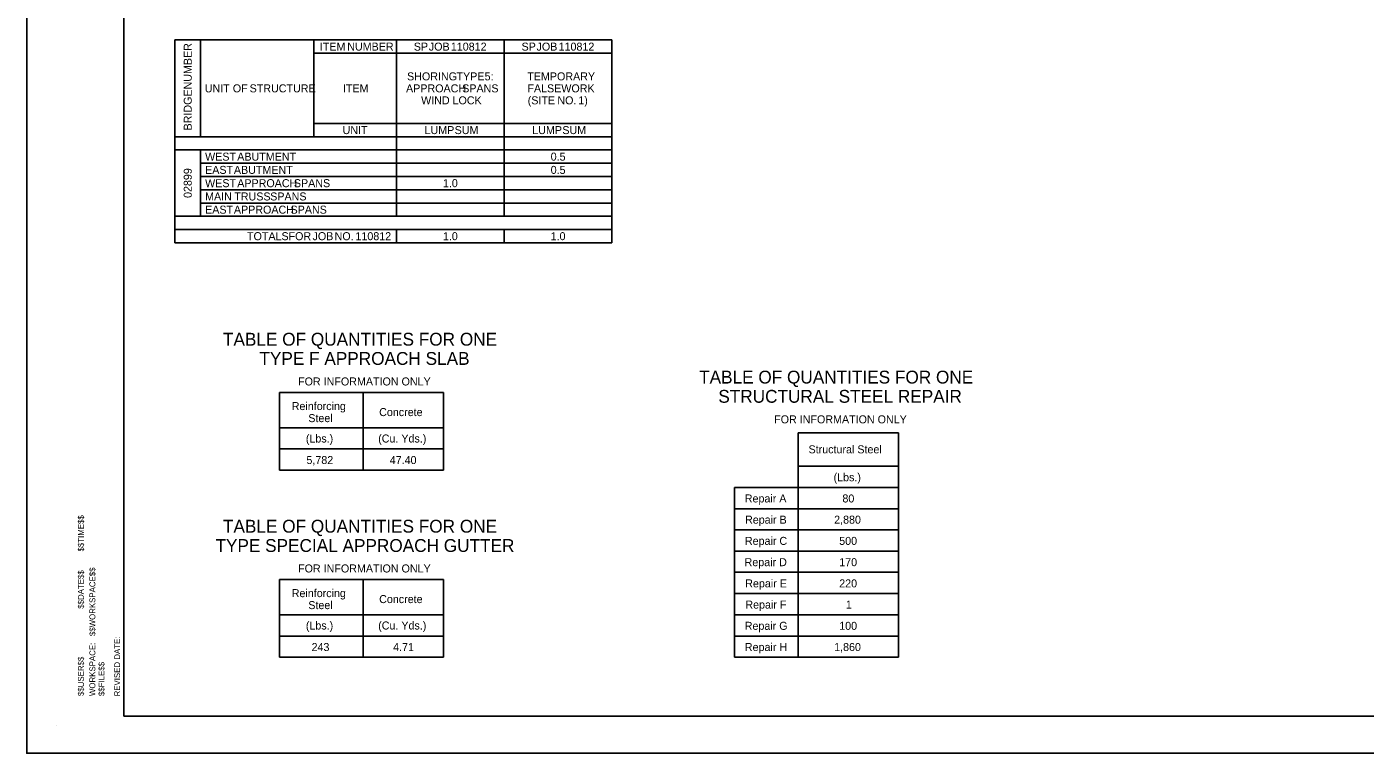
# Model space of a CAD drawing. Extents: x 188 to 14744886, y 129 to 1829278.
# Drawn here: x 187.88 to 208.75, y 128.51 to 139.85 of the extents above; entities that cross this region are included whole.
import ezdxf

# ---------------------------------------------------------------- set-up
doc = ezdxf.new("R2010")
doc.units = 0
for name, color, linetype in [('B_Text', 7, 'Continuous'), ('B_Title Text', 7, 'Continuous'), ('R_Border', 7, 'Continuous'), ('R_No Plot', 7, 'Continuous')]:
    doc.layers.add(name, color=color, linetype=linetype)

msp = doc.modelspace()

# ---------------------------------------------------------------- linework, layer by layer
at = {"layer": 'B_Text'}
for p, q in [((190.192, 139.64), (197.006, 139.64)), ((190.192, 139.64), (197.006, 139.64)), ((190.192, 136.476), (190.192, 139.64)), ((190.593, 138.131), (190.593, 139.64)), ((192.357, 138.131), (192.357, 139.64)), ((192.357, 138.131), (192.357, 139.64)), ((193.647, 136.89), (193.647, 139.64)), ((195.326, 136.89), (195.326, 139.64)), ((197.006, 136.476), (197.006, 139.64)), ((197.006, 136.476), (197.006, 139.64)), ((192.357, 139.433), (197.006, 139.433)), ((192.357, 138.338), (197.006, 138.338)), ((190.192, 138.131), (197.006, 138.131)), ((190.192, 137.924), (197.006, 137.924)), ((190.593, 136.89), (190.593, 137.924)), ((190.593, 137.717), (197.006, 137.717)), ((190.593, 137.51), (197.006, 137.51)), ((190.593, 137.303), (197.006, 137.303)), ((190.593, 137.096), (197.006, 137.096)), ((190.192, 136.89), (197.006, 136.89)), ((190.192, 136.683), (197.006, 136.683)), ((193.647, 136.476), (193.647, 136.683)), ((195.326, 136.476), (195.326, 136.683)), ((190.192, 136.476), (197.006, 136.476)), ((193.128, 132.928), (193.128, 134.139)), ((191.823, 133.26), (194.381, 133.26)), ((199.909, 132.991), (201.475, 132.991)), ((198.916, 132.329), (201.475, 132.329)), ((198.916, 131.998), (201.475, 131.998)), ((198.916, 131.667), (201.475, 131.667)), ((198.916, 131.336), (201.475, 131.336)), ((193.128, 130.011), (193.128, 131.222)), ((198.916, 131.005), (201.475, 131.005)), ((198.916, 130.673), (201.475, 130.673)), ((191.823, 130.342), (194.381, 130.342)), ((198.916, 130.342), (201.475, 130.342))]:
    msp.add_line(p, q, dxfattribs=at)
at = {"layer": 'B_Title Text'}
for p, q in [((191.823, 134.139), (194.381, 134.139)), ((191.823, 132.928), (191.823, 134.139)), ((194.381, 132.928), (194.381, 134.139)), ((191.823, 133.591), (194.381, 133.591)), ((199.909, 130.011), (199.909, 133.513)), ((199.909, 133.513), (201.475, 133.513)), ((201.475, 130.011), (201.475, 133.513)), ((191.823, 132.928), (194.381, 132.928)), ((198.916, 132.66), (201.475, 132.66)), ((198.916, 130.011), (198.916, 132.66)), ((191.823, 131.222), (194.381, 131.222)), ((191.823, 130.011), (191.823, 131.222)), ((194.381, 130.011), (194.381, 131.222)), ((191.823, 130.673), (194.381, 130.673)), ((191.823, 130.011), (194.381, 130.011)), ((198.916, 130.011), (201.475, 130.011))]:
    msp.add_line(p, q, dxfattribs=at)
at = {"layer": 'R_Border'}
for p, q in [((189.399, 129.091), (189.399, 149.937)), ((221.306, 129.091), (189.399, 129.091)), ((188.351, 128.942), (188.351, 128.942))]:
    msp.add_line(p, q, dxfattribs=at)
at = {"layer": 'R_No Plot'}
msp.add_lwpolyline([(187.883, 150.514), (221.883, 150.514), (221.883, 128.514), (187.883, 128.514)], close=True, dxfattribs=at)

# ---------------------------------------------------------------- texts
at = {"layer": 'B_Text'}
for s, height, p in [('ITEM', 0.1248, (192.452, 139.474)), (' NUMBER', 0.1248, (192.833, 139.474)), ('SP', 0.1248, (193.917, 139.474)), (' JOB', 0.1248, (194.105, 139.474)), (' 110812', 0.1248, (194.448, 139.474)), ('SP', 0.1248, (195.597, 139.474)), (' JOB', 0.1248, (195.784, 139.474)), (' 110812', 0.1248, (196.128, 139.474)), ('SHORING', 0.1248, (193.812, 139.01)), (' TYPE', 0.1248, (194.536, 139.01)), (' 5:', 0.1248, (194.974, 139.01)), ('TEMPORARY', 0.1248, (195.686, 139.01)), ('UNIT', 0.1248, (190.658, 138.823)), (' OF', 0.1248, (191.049, 138.823)), (' STRUCTURE', 0.1248, (191.311, 138.823)), ('ITEM', 0.1248, (192.812, 138.823)), ('APPROACH', 0.1248, (193.796, 138.823)), ('WIND', 0.1248, (194.031, 138.636)), (' LOCK', 0.1248, (194.475, 138.636)), (' SPANS', 0.1248, (194.625, 138.823)), ('FALSEWORK', 0.1248, (195.688, 138.823)), ('(SITE', 0.1248, (195.693, 138.636)), (' NO.', 0.1248, (196.109, 138.636)), (' 1)', 0.1248, (196.435, 138.636)), ('UNIT', 0.1248, (192.807, 138.172)), ('LUMP', 0.1248, (194.085, 138.172)), (' SUM', 0.1248, (194.507, 138.172)), ('LUMP', 0.1248, (195.764, 138.172)), (' SUM', 0.1248, (196.186, 138.172)), (' WEST', 0.1248, (190.617, 137.758)), (' ABUTMENT', 0.1248, (191.118, 137.758)), ('0.5', 0.1248, (196.051, 137.758)), (' EAST', 0.1248, (190.617, 137.551)), (' ABUTMENT', 0.1248, (191.066, 137.551)), ('0.5', 0.1248, (196.051, 137.551)), (' WEST', 0.1248, (190.617, 137.344)), (' APPROACH', 0.1248, (191.118, 137.344)), (' SPANS', 0.1248, (192.001, 137.344)), ('1.0', 0.1248, (194.371, 137.344)), (' MAIN', 0.1248, (190.617, 137.137)), (' TRUSS', 0.1248, (191.072, 137.137)), (' SPANS', 0.1248, (191.632, 137.137)), (' EAST', 0.1248, (190.617, 136.931)), (' APPROACH', 0.1248, (191.066, 136.931)), (' SPANS', 0.1248, (191.949, 136.931)), ('TOTALS', 0.1248, (191.317, 136.517)), (' FOR', 0.1248, (191.918, 136.517)), (' JOB', 0.1248, (192.292, 136.517)), (' NO.', 0.1248, (192.636, 136.517)), (' 110812', 0.1248, (192.961, 136.517)), ('1.0', 0.1248, (194.371, 136.517)), ('1.0', 0.1248, (196.05, 136.517)), ('FOR INFORMATION ONLY', 0.1248, (192.113, 134.251)), ('Reinforcing', 0.1248, (192.014, 133.867)), ('Steel', 0.1248, (192.272, 133.679)), ('Concrete ', 0.1248, (193.377, 133.773)), ('FOR INFORMATION ONLY', 0.1248, (199.535, 133.66)), ('(Lbs.)', 0.1248, (192.234, 133.361)), ('(Cu. Yds.)', 0.1248, (193.362, 133.361)), ('5,782', 0.1248, (192.243, 133.025)), ('47.40', 0.1248, (193.542, 133.025)), ('Structural Steel', 0.1248, (200.071, 133.192)), ('(Lbs.)', 0.1248, (200.461, 132.757)), ('Repair A', 0.1248, (199.077, 132.426)), ('80', 0.1248, (200.599, 132.426)), ('Repair B', 0.1248, (199.081, 132.095)), ('2,880', 0.1248, (200.47, 132.095)), ('Repair C', 0.1248, (199.079, 131.764)), ('500', 0.1248, (200.549, 131.764)), ('FOR INFORMATION ONLY', 0.1248, (192.113, 131.334)), ('Repair D', 0.1248, (199.074, 131.432)), ('170', 0.1248, (200.549, 131.432)), ('Reinforcing', 0.1248, (192.014, 130.949)), ('Repair E', 0.1248, (199.084, 131.101)), ('220', 0.1248, (200.549, 131.101)), ('Steel', 0.1248, (192.272, 130.762)), ('Concrete ', 0.1248, (193.377, 130.856)), ('Repair F', 0.1248, (199.086, 130.77)), ('1', 0.125, (200.652, 130.77)), ('(Lbs.)', 0.1248, (192.234, 130.444)), ('(Cu. Yds.)', 0.1248, (193.362, 130.444)), ('Repair G', 0.1248, (199.076, 130.439)), ('100', 0.1248, (200.549, 130.439)), ('243', 0.1248, (192.323, 130.108)), ('4.71', 0.1248, (193.595, 130.108)), ('Repair H', 0.1248, (199.078, 130.108)), ('1,860', 0.1248, (200.47, 130.108))]:
    msp.add_text(s, height=height, dxfattribs=at).set_placement(p)
for s, p in [(' NUMBER', (190.455, 138.822)), ('BRIDGE', (190.455, 138.229)), ('02899', (190.455, 137.176))]:
    msp.add_text(s, height=0.1248, rotation=90, dxfattribs=at).set_placement(p)
at = {"layer": 'B_Title Text'}
for s, p in [('TABLE OF QUANTITIES FOR ONE', (190.942, 134.872)), ('TYPE F APPROACH SLAB', (191.51, 134.572)), ('TABLE OF QUANTITIES FOR ONE', (198.365, 134.281)), ('STRUCTURAL STEEL REPAIR', (198.664, 133.981)), ('TABLE OF QUANTITIES FOR ONE', (190.942, 131.955)), ('TYPE SPECIAL APPROACH GUTTER', (190.825, 131.654))]:
    msp.add_text(s, height=0.2004, dxfattribs=at).set_placement(p)
at = {"layer": 'R_Border'}
for s, p in [('$$TIME$$', (188.773, 131.661)), ('$$DATE$$', (188.773, 130.768)), ('$$WORKSPACE$$', (188.952, 130.341)), ('WORKSPACE:', (188.952, 129.406)), ('REVISED DATE:', (189.338, 129.4)), ('$$USER$$', (188.773, 129.406)), ('$$FILE$$', (189.094, 129.406))]:
    msp.add_text(s, height=0.0918, rotation=90, dxfattribs=at).set_placement(p)

doc.saveas('drawing.dxf')
